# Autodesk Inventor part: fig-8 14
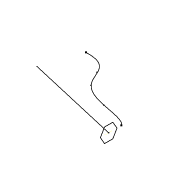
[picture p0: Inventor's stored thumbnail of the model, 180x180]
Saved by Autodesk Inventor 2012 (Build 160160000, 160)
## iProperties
Created: 2004-05
Part Number: fig-8 14
Document SubType Name: Modeling
Designer: CADCIM Technologies
Manufacturer: Standard
Standards Organization: Custom
Density: 1 g/cm^3
Material: Default
Author: CADCIM Technologies
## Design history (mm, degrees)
workplane "Work Plane2"
sketch "Sketch7"
  geometry: L1 (-42.583, 6.068)-(-42.583, 0.37) reference; 5 further points
  constraints: 1 point on line, 5 other
sketch "Sketch8"
  geometry: L1 (-42.583, 3.219)-(-107.269, 18.236); L2 (-42.583, 6.068)-(-42.583, 0.37) reference
  constraints: 2 end point, 1 midpoint
sketch "Sketch2"
  geometry: L1 (-5.697, 0)-(-2.849, 4.934); L2 (-2.849, 4.934)-(2.849, 4.934); L3 (2.849, 4.934)-(5.697, 0); L4 (5.697, 0)-(2.849, -4.934); L5 (2.849, -4.934)-(-2.849, -4.934); L6 (-2.849, -4.934)-(-5.697, 0); 2 further points
  constraints: 12 end point, 1 coincident, 12 other
